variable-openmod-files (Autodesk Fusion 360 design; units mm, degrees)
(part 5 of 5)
sketch "Sketch21" plane through (0, 0, 36) normal (0, 0, 1) x axis (-1, 0, 0)
  line L1 (-70.6699, 179.8205) -> (-76.1699, 170.2942)
  line L2 (-80.6292, 185.5705) -> (-70.6699, 179.8205)
  line L3 (-90.4356, 168.5852) -> (-80.6292, 185.5705)
  line L4 (-86.2462, 149.3972) -> (-90.4356, 168.5852)
  curve K1 (-86.2462, 149.3972) -> (0, 72.5)
  curve K2 (86.2462, 149.3972) -> (0, 72.5)
  line L5 (90.4356, 168.5852) -> (86.2462, 149.3972)
  line L6 (80.6292, 185.5705) -> (90.4356, 168.5852)
  line L7 (70.6699, 179.8205) -> (80.6292, 185.5705)
  line L8 (74.1699, 173.7583) -> (70.6699, 179.8205)
  line L9 (81.2713, 177.8583) -> (74.1699, 173.7583)
  line L10 (86.3713, 169.0249) -> (81.2713, 177.8583)
  line L11 (85.989, 166.4546) -> (86.3713, 169.0249)
  curve K3 (0, 74) -> (85.989, 166.4546)
  curve K4 (0, 74) -> (-85.989, 166.4546)
  line L12 (-86.3713, 169.0249) -> (-85.989, 166.4546)
  line L13 (-83.2713, 174.3942) -> (-86.3713, 169.0249)
  line L14 (-76.1699, 170.2942) -> (-83.2713, 174.3942)
  line L15 (-75.4199, 171.5933) -> (-76.1699, 170.2942)
  line L16 (-78.0179, 173.0933) -> (-75.4199, 171.5933)
  line L17 (-78.0179, 173.0933) -> (-78.7679, 171.7942)
  line L18 (-76.9279, 172.4639) -> (-78.7679, 171.7942)
  line L19 (-76.8098, 171.7942) -> (-78.7679, 171.7942)
  line L20 (-76.6681, 172.3139) -> (-76.9279, 172.4639)
  line L21 (-76.3281, 170.3856) -> (-76.6681, 172.3139)
  line L22 (-74.71, 172.3139) -> (-76.6681, 172.3139)
  line L23 (0, 74) -> (0, 72.5)
  line L24 (78.0179, 173.0933) -> (78.7679, 171.7942)
  line L25 (76.6681, 172.3139) -> (76.9279, 172.4639)
  line L26 (74.71, 172.3139) -> (76.6681, 172.3139)
  line L27 (78.0179, 173.0933) -> (75.4199, 171.5933)
  line L28 (76.9279, 172.4639) -> (78.7679, 171.7942)
  line L29 (76.3281, 170.3856) -> (76.6681, 172.3139)
  line L30 (75.4199, 171.5933) -> (76.1699, 170.2942)
  line L31 (76.8098, 171.7942) -> (78.7679, 171.7942)
  line L32 (76.1699, 170.2942) -> (78.7679, 171.7942)
  point P2 (-76.1699, 170.2942)
  point P20 (-76.1699, 170.2942)
  point P25 (-76.9279, 172.4639)
  point P28 (-76.3281, 170.3856)
  point P7 (0, 72.5)
  point P30 (0, 72.5)
  point P16 (0, 74)
  point P31 (0, 74)
  point P40 (76.1699, 170.2942)
  point P34 (76.1699, 170.2942)
  point P21 (-75.4199, 171.5933)
  point P36 (75.4199, 171.5933)
  point P22 (-78.0179, 173.0933)
  point P42 (78.0179, 173.0933)
  point P23 (-78.7679, 171.7942)
  point P35 (78.7679, 171.7942)
  point P24 (-78.0179, 173.0933)
  point P38 (78.0179, 173.0933)
  point P33 (76.9279, 172.4639)
  point P26 (-76.8098, 171.7942)
  point P32 (76.8098, 171.7942)
  point P27 (-76.6681, 172.3139)
  point P39 (76.6681, 172.3139)
  point P41 (76.3281, 170.3856)
  point P29 (-74.71, 172.3139)
  point P37 (74.71, 172.3139)
  point P43 (76.1699, 170.2942)
  coincident P2 P20
  perpendicular L14 L15
  perpendicular L1 L16
  horizontal L19
  coincident L16 P25
  parallel L16 L20
  horizontal L22
  coincident L14 P28
  coincident P7 P30
  coincident P16 P31
  symmetric P2 L23 P40
  symmetric P20 L23 P34
  symmetric P21 L23 P36
  symmetric P22 L23 P42
  symmetric P23 L23 P35
  symmetric P24 L23 P38
  symmetric P25 L23 P33
  symmetric P26 L23 P32
  symmetric P27 L23 P39
  symmetric P28 L23 P41
  symmetric P29 L23 P37
  coincident P40 P43
  perpendicular L30 L32
  dimension "d657" distance P20 P21 = 1.5
  dimension "d658" distance P21 P22 = 3
  dimension "d659" = -3
  dimension "d660" angle L18 L19 = 20
  dimension "d661" distance P25 P27 = 0.3
  dimension "d662" angle L21 L22 = 80
sketch "Sketch22" plane through (-130.0009, -75.0561, 0) normal (0.866, 0.5, 0) x axis (-0.5, 0.866, 0)
  line L1 (-113.3942, 1) -> (-120.3942, 1)
  line L2 (-113.3942, 35) -> (-113.3942, 1)
  line L3 (-120.3942, 35) -> (-113.3942, 35)
  line L4 (-120.3942, 1) -> (-120.3942, 35)
  line L5 (-109.3942, 1) -> (-120.3942, 1)
  line L6 (-109.3942, 8.4) -> (-109.3942, 1)
  line L7 (-120.3942, 8.4) -> (-109.3942, 8.4)
  line L8 (-120.3942, 1) -> (-120.3942, 8.4)
  line L9 (-109.3942, 1) -> (-120.3942, 1)
  line L10 (-109.3942, 0) -> (-109.3942, 1)
  line L11 (-120.3942, 0) -> (-109.3942, 0)
  line L12 (-120.3942, 1) -> (-120.3942, 0)
  line L13 (-113.3942, 0) -> (-113.3942, 1)
  line L14 (-113.3942, 12.4) -> (-109.3942, 8.4)
  line L15 (-115.051, 8.4) -> (-109.3942, 8.4)
  point P2 (-120.3942, 1)
  point P6 (-120.3942, 1)
  point P10 (-120.3942, 1)
  point P3 (-113.3942, 1)
  point P14 (-113.3942, 1)
  point P15 (-113.3942, 0)
  point P16 (-113.3942, 12.4)
  point P7 (-109.3942, 1)
  point P9 (-120.3942, 8.4)
  point P13 (-120.3942, 0)
  horizontal L5
  vertical L6
  horizontal L7
  vertical L8
  coincident P2 P6
  horizontal L9
  vertical L10
  horizontal L11
  vertical L12
  coincident P2 P10
  coincident P3 P14
  coincident L11 P15
  perpendicular L11 L13
  horizontal L15
  coincident L2 P16
  dimension "d663" distance P6 P7 = 11
  dimension "d664" distance P6 P9 = 7.4
  dimension "d665" distance P10 P13 = 1
  dimension "d666" angle L14 L15 = 45
extrude "Extrude39" add sketch "Sketch22" profile of L2 L5 L6 L7 L9 L10 L11 L13 L14 against normal blind 9.2
extrude "Extrude40" cut of existing geometry blind -4
extrude "Extrude41" cut sketch "Sketch21" profile of L14 L16 L18 L20 L21 L25 L27 L28 L29 L32 against normal blind 36
sketch "40mm adapter for 52mm" plane through (0, 0, 0) normal (0, 0, 1) x axis (1, 0, 0)
  circle C1 centre (180, 25) radius 24.9
  circle C2 centre (180, 25) radius 20.15
  circle C3 centre (180, 25) radius 18.5
  circle C4 centre (180, 25) radius 21.5
  concentric C1 C2
  concentric C2 C3
  concentric C1 C4
  dimension "d673" diameter C1 = 49.8
  dimension "d674" diameter C2 = 40.3
  dimension "d675" diameter C3 = 37
  dimension "d676" diameter C4 = 43
extrude "Extrude7" new body sketch "40mm adapter for 52mm" profile of C2 C3 along normal blind 1.5
extrude "Extrude8" add sketch "40mm adapter for 52mm" profile of C2 C4 along normal blind 3
extrude "Extrude9" add sketch "40mm adapter for 52mm" profile of C1 C4 along normal blind 2
component_from_bodies "Body->Comp3"
sketch "Sketch1" plane through (0, 0, 0) normal (0, 0, 1) x axis (1, 0, 0)
  line L1 (219.4437, 9.4437) -> (235, 25)
  line L2 (213, 25) -> (235, 25)
  line L3 (250.5563, 9.4437) -> (235, 25)
  line L4 (257, 25) -> (235, 25)
  circle C1 centre (235, 25) radius 22
  circle C2 centre (235, 25) radius 20.1
  circle C3 centre (235, 25) radius 18
  point P2 (235, 25)
  point P4 (235, 25)
  point P5 (219.4437, 9.4437)
  point P3 (235, 25)
  point P7 (235, 25)
  point P8 (250.5563, 9.4437)
  concentric C1 C2
  horizontal L2
  coincident P2 P4
  coincident C1 P5
  horizontal L4
  coincident P3 P7
  coincident C1 P8
  concentric C2 C3
  dimension "d683" diameter C1 = 44
  dimension "d684" diameter C2 = 40.2
  dimension "d685" angle L1 L2 = 45
  dimension "d686" angle L3 L4 = 45
  dimension "d687" diameter C3 = 36
extrude "Extrude1" new body sketch "Sketch1" profile of C1 C2 L1 L3 along normal blind 6 bodies "40mm Top adapter"
extrude "Extrude2" add sketch "Sketch1" profile of C2 L1 L3 C3 along normal blind 4
copy_paste_bodies "CopyPasteBodies1"
move "Move1"
offset_faces "OffsetFaces1" distance 2
offset_faces "OffsetFaces2" distance -2
copy_paste_bodies "CopyPasteBodies3"
move "Move3"
offset_faces "OffsetFaces3" distance 0.5
offset_faces "OffsetFaces4" distance -0.5
position "Position1"
copy_paste_bodies "CopyPasteBodies4"
move "Move3"
component_from_bodies "Body->Comp4"
copy_paste_bodies "CutPasteBodies1"
extrude "Extrude1" cut of existing geometry blind -1.5
move_face "MoveFace1"
move_face "MoveFace2"
move "Move4"
move "Move5"
move "Move6"
move "Move7"
move "Move8"
move "Move4"
move "Move1"
move "Move5"
move "Move2"
move "Move6"
move "Move7"
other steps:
base_feature "Base Feature1" bodies "40mm Bottom adapter"
base_feature "Base Feature1" bodies "50mm Pad Mount"
base_feature "Base Feature2" bodies "40mm Pad Mount", "45mm Pad Mount", "52mm Pad Mount", "44mm Pad Mount"
base_feature "Base Feature2" bodies "40mm Bottom adapter", "40mm Top adapter", "44mm Bottom adapter", "44mm Top adapter"
base_feature "Base Feature4" bodies "44mm Bottom adapter", "44mm Top adapter", "45mm Bottom adapter", "45mm Top adapter"
base_feature "Base Feature1" bodies "50mm Pad Mount"
base_feature "Base Feature1" bodies "Pad Mount"
base_feature "Base Feature2" bodies "Driver Clamp"
base_feature "Base Feature4" bodies "50mm Pad Mount", "40mm Pad Mount", "52mm Pad Mount", "44mm Pad Mount", "45mm Pad Mount"
base_feature "Base Feature2" bodies "Driver Clamp", "Driver Clamp (1)"
base_feature "Base Feature3" bodies "Closed Shell", "Closed Shell (1)"
base_feature "Base Feature4" bodies "Open Shell", "Custom Shell Body"
base_feature "Base Feature1" bodies "Pad Mount", "40mm Pad Mount"
base_feature "Base Feature2" bodies "Driver Clamp", "40mm Middle Body"
base_feature "Base Feature3" bodies "Driver Clamp (1)", "Pad Mount (1)", "52mm Middle Body", "52mm Pad Mount"
base_feature "Base Feature4" bodies "Pad Mount (2)", "Driver Clamp (2)", "44mm Pad Mount", "44mm Middle Body"
base_feature "Base Feature5" bodies "44mm Pad Mount", "44mm Driver Clamp", "45mm Pad Mount", "45mm Middle Body"
base_feature "Base Feature5" bodies "Custom Shell Grill", "Custom Shell Closed Grill"
create_component "CreateComponent1"
remove_body "RemoveBody1"
create_component "CreateComponent2"
create_component "CreateComponent3"
remove_body "RemoveBody2"
remove_body "RemoveBody3"
create_component "CreateComponent4"
remove_body "RemoveBody4"
create_component "CreateComponent5"
remove_body "RemoveBody5"
remove_body "RemoveBody6"
remove_body "RemoveBody7"
remove_body "RemoveBody8"
remove_body "RemoveBody9"
named bodies: "50mm Pad Mount", "50mm Middle Body", "Closed Shell", "Driver Clamp", "Driver Clamp (1)", "Closed Shell (1) (1)", "Closed Shell (1) (2)", "Closed Shell (1) (3)", "Open Shell", "Headband Arc", "Yoke", "Screw Holder", "Headband Clip", "Pad Mount", "40mm Pad Mount", "40mm Middle Body", "Pad Mount (1)", "52mm Middle Body", "52mm Pad Mount", "Pad Mount (2)", "Driver Clamp (2)", "44mm Pad Mount", "44mm Middle Body", "44mm Driver Clamp", "45mm Pad Mount", "45mm Middle Body", "TPU Suspension Pad", "45cm 1.75mm Unprinted TPU", "Closed Shell (1)", "40mm Bottom adapter", "40mm Top adapter", "44mm Bottom adapter", "44mm Top adapter", "45mm Bottom adapter", "45mm Top adapter", "Custom Shell Body", "Custom Shell Open Grill", "Custom Shell Grill", "Custom Shell Closed Grill"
